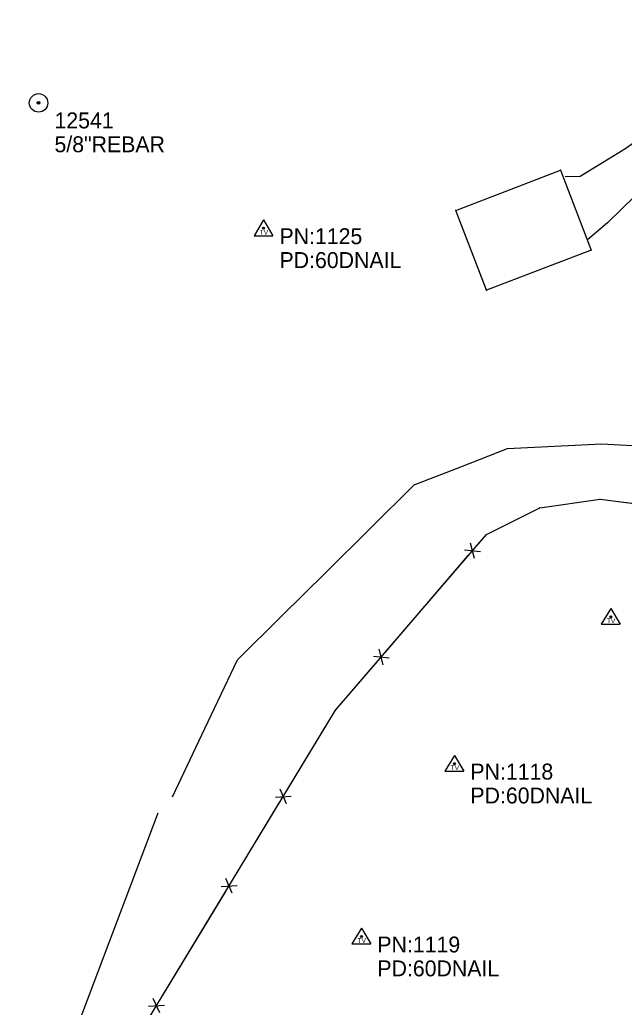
# Model space of a CAD drawing. Extents: x 1050807 to 1053552, y 395828 to 398415.
# Drawn here: x 1051876 to 1052065.9, y 397198.7 to 397508.9 of the extents above; entities that cross this region are included whole.
import ezdxf

# ---------------------------------------------------------------- set-up
doc = ezdxf.new("R2010")
doc.units = 0
for name, color, linetype in [('S_BUILDING', 7, 'Continuous'), ('S_DITCHLINE', 7, 'Continuous'), ('S_DRIVEWAY', 7, 'Continuous'), ('S_FENCE', 7, 'Continuous'), ('S_IRON_PIN', 7, 'Continuous'), ('S_IRON_PIN_ANNOT', 7, 'Continuous'), ('S_MSC_PT_SYM', 7, 'Continuous'), ('S_SECONDARY_CTL', 7, 'Continuous'), ('S_SECONDARY_CTL_ANNOT', 7, 'Continuous'), ('S_STR_PT_SYM', 7, 'Continuous')]:
    doc.layers.add(name, color=color, linetype=linetype)

msp = doc.modelspace()

# ---------------------------------------------------------------- linework, layer by layer
at = {"layer": 'S_BUILDING'}
for p, q in [((1052012.94, 397449.05), (1052045.8, 397461.69)), ((1052045.8, 397461.69), (1052055.46, 397436.58)), ((1052022.48, 397424.27), (1052012.94, 397449.05)), ((1052022.6, 397423.94), (1052012.94, 397449.05)), ((1052055.46, 397436.58), (1052022.6, 397423.94))]:
    msp.add_line(p, q, dxfattribs=at)
at = {"layer": 'S_DITCHLINE'}
for points in [[(1051923.97, 397264.82), (1051934.15, 397286.32), (1051944.33, 397307.83), (1051958.22, 397321.57), (1051972.1, 397335.31), (1051985.98, 397349.06), (1051999.87, 397362.8), (1052014.51, 397368.54), (1052029.14, 397374.28), (1052043.96, 397375.01), (1052058.77, 397375.75), (1052082, 397374.5), (1052105.23, 397373.25), (1052125.17, 397384.42), (1052145.11, 397395.59), (1052158.93, 397404.03), (1052172.75, 397412.47), (1052180.81, 397417.01)], [(1051875.96, 397128.93), (1051879.28, 397151.76), (1051885.74, 397169.79), (1051892.2, 397187.82), (1051899.01, 397205.81), (1051905.81, 397223.8), (1051912.61, 397241.79), (1051919.41, 397259.77)]]:
    msp.add_lwpolyline(points, dxfattribs=at)
at = {"layer": 'S_DRIVEWAY'}
for points in [[(1052145.24, 397508.93), (1052124, 397500.53), (1052103.96, 397490.66), (1052083.92, 397480.8), (1052066, 397468.26), (1052052.01, 397459.72), (1052047.34, 397459.64)], [(1052148.91, 397496.27), (1052135.7, 397491.43), (1052122.5, 397486.6), (1052110.72, 397480.8), (1052098.93, 397475), (1052087.27, 397468.16), (1052073.58, 397457.8), (1052060.55, 397445.18), (1052054.3, 397439.83)]]:
    msp.add_lwpolyline(points, dxfattribs=at)
at = {"layer": 'S_FENCE'}
for p, q in [((1052022.59, 397347.28), (1052039.3, 397355.63)), ((1052039.3, 397355.63), (1052058.28, 397358.31)), ((1052058.28, 397358.31), (1052107.7, 397352.14)), ((1051975.19, 397292.08), (1052022.59, 397347.28)), ((1052018.81, 397339.73), (1052017.57, 397344.57)), ((1052018.81, 397339.73), (1052017.57, 397344.57)), ((1052015.7, 397342.4), (1052020.67, 397341.91)), ((1052015.7, 397342.4), (1052020.67, 397341.91)), ((1051987.04, 397309.02), (1051992.01, 397308.52)), ((1051987.04, 397309.02), (1051992.01, 397308.52)), ((1051990.14, 397306.35), (1051988.9, 397311.19)), ((1051990.14, 397306.35), (1051988.9, 397311.19)), ((1051947.34, 397246.14), (1051975.19, 397292.08)), ((1051959.75, 397262.65), (1051957.73, 397267.23)), ((1051959.75, 397262.65), (1051957.73, 397267.23)), ((1051956.25, 397264.78), (1051961.23, 397265.1)), ((1051956.25, 397264.78), (1051961.23, 397265.1)), ((1051907.52, 397180.44), (1051947.34, 397246.14)), ((1051942.73, 397234.58), (1051940.71, 397239.15)), ((1051942.73, 397234.58), (1051940.71, 397239.15)), ((1051939.23, 397236.7), (1051944.22, 397237.03)), ((1051939.23, 397236.7), (1051944.22, 397237.03)), ((1051919.93, 397196.96), (1051917.91, 397201.54)), ((1051919.93, 397196.96), (1051917.91, 397201.54)), ((1051916.43, 397199.08), (1051921.42, 397199.41)), ((1051916.43, 397199.08), (1051921.42, 397199.41))]:
    msp.add_line(p, q, dxfattribs=at)
for points in [[(1052022.59, 397347.28), (1052039.3, 397355.63)], [(1052022.59, 397347.28), (1052039.3, 397355.63)], [(1052039.3, 397355.63), (1052058.28, 397358.31)], [(1052039.3, 397355.63), (1052058.28, 397358.31)], [(1052058.28, 397358.31), (1052078.13, 397355.83)], [(1052058.28, 397358.31), (1052078.13, 397355.83)], [(1052019.12, 397343.24), (1052022.59, 397347.28)], [(1052019.12, 397343.24), (1052022.59, 397347.28)], [(1051990.83, 397310.29), (1052016.88, 397340.64)], [(1051990.83, 397310.29), (1052016.88, 397340.64)], [(1051975.19, 397292.08), (1051988.22, 397307.25)], [(1051975.19, 397292.08), (1051988.22, 397307.25)], [(1051959.78, 397266.65), (1051975.19, 397292.08)], [(1051959.78, 397266.65), (1051975.19, 397292.08)], [(1051947.34, 397246.14), (1051957.7, 397263.23)], [(1051947.34, 397246.14), (1051957.7, 397263.23)], [(1051942.46, 397238.09), (1051947.34, 397246.14)], [(1051942.46, 397238.09), (1051947.34, 397246.14)], [(1051919.96, 397200.96), (1051940.68, 397235.15)], [(1051919.96, 397200.96), (1051940.68, 397235.15)]]:
    msp.add_lwpolyline(points, dxfattribs=at)
at = {"layer": 'S_IRON_PIN'}
for radius in [2.91, 0.411, 0.262, 0.212, 0.145, 0.0822, 0.0581]:
    msp.add_circle((1051881.87, 397482.81), radius, dxfattribs=at)
at = {"layer": 'S_MSC_PT_SYM'}
for points in [[(1052039.3, 397355.63), (1052039.3, 397355.68), (1052039.3, 397355.63), (1052039.25, 397355.63), (1052039.3, 397355.63), (1052039.3, 397355.58), (1052039.3, 397355.63), (1052039.35, 397355.63)], [(1052058.28, 397358.31), (1052058.28, 397358.36), (1052058.28, 397358.31), (1052058.23, 397358.31), (1052058.28, 397358.31), (1052058.28, 397358.26), (1052058.28, 397358.31), (1052058.33, 397358.31)], [(1052022.59, 397347.28), (1052022.59, 397347.33), (1052022.59, 397347.28), (1052022.54, 397347.28), (1052022.59, 397347.28), (1052022.59, 397347.23), (1052022.59, 397347.28), (1052022.64, 397347.28)], [(1051975.19, 397292.08), (1051975.19, 397292.13), (1051975.19, 397292.08), (1051975.14, 397292.08), (1051975.19, 397292.08), (1051975.19, 397292.03), (1051975.19, 397292.08), (1051975.24, 397292.08)], [(1051947.34, 397246.14), (1051947.34, 397246.19), (1051947.34, 397246.14), (1051947.29, 397246.14), (1051947.34, 397246.14), (1051947.34, 397246.09), (1051947.34, 397246.14), (1051947.39, 397246.14)]]:
    msp.add_lwpolyline(points, dxfattribs=at)
at = {"layer": 'S_SECONDARY_CTL'}
for p, q in [((1051952.56, 397446.05), (1051949.55, 397441.1)), ((1051952.56, 397446.05), (1051955.51, 397441.1)), ((1051949.55, 397441.1), (1051955.51, 397441.1)), ((1052061.61, 397324.02), (1052058.6, 397319.07)), ((1052061.61, 397324.02), (1052064.56, 397319.07)), ((1052058.6, 397319.07), (1052064.56, 397319.07)), ((1052012.53, 397277.87), (1052009.52, 397272.91)), ((1052012.53, 397277.87), (1052015.48, 397272.91)), ((1052009.52, 397272.91), (1052015.48, 397272.91)), ((1051983.31, 397223.57), (1051980.3, 397218.62)), ((1051983.31, 397223.57), (1051986.26, 397218.62)), ((1051980.3, 397218.62), (1051986.26, 397218.62))]:
    msp.add_line(p, q, dxfattribs=at)
for centre, radius in [((1051952.56, 397443.44), 0.311), ((1051952.56, 397443.44), 0.183), ((1051952.56, 397443.44), 0.103), ((1052061.61, 397321.41), 0.311), ((1052061.61, 397321.41), 0.183), ((1052061.61, 397321.41), 0.103), ((1052012.53, 397275.26), 0.311), ((1052012.53, 397275.26), 0.183), ((1052012.53, 397275.26), 0.103), ((1051983.31, 397220.96), 0.311), ((1051983.31, 397220.96), 0.183), ((1051983.31, 397220.96), 0.103)]:
    msp.add_circle(centre, radius, dxfattribs=at)
at = {"layer": 'S_STR_PT_SYM'}
for points in [[(1052045.8, 397461.69), (1052045.8, 397461.74), (1052045.8, 397461.69), (1052045.75, 397461.69), (1052045.8, 397461.69), (1052045.8, 397461.64), (1052045.8, 397461.69), (1052045.85, 397461.69)], [(1052012.94, 397449.05), (1052012.94, 397449.1), (1052012.94, 397449.05), (1052012.89, 397449.05), (1052012.94, 397449.05), (1052012.94, 397449), (1052012.94, 397449.05), (1052012.99, 397449.05)], [(1052012.94, 397449.05), (1052012.94, 397449.1), (1052012.94, 397449.05), (1052012.89, 397449.05), (1052012.94, 397449.05), (1052012.94, 397449), (1052012.94, 397449.05), (1052012.99, 397449.05)], [(1052055.46, 397436.58), (1052055.46, 397436.63), (1052055.46, 397436.58), (1052055.41, 397436.58), (1052055.46, 397436.58), (1052055.46, 397436.53), (1052055.46, 397436.58), (1052055.51, 397436.58)], [(1052022.48, 397424.27), (1052022.48, 397424.32), (1052022.48, 397424.27), (1052022.43, 397424.27), (1052022.48, 397424.27), (1052022.48, 397424.22), (1052022.48, 397424.27), (1052022.53, 397424.27)], [(1052022.6, 397423.94), (1052022.6, 397423.99), (1052022.6, 397423.94), (1052022.55, 397423.94), (1052022.6, 397423.94), (1052022.6, 397423.89), (1052022.6, 397423.94), (1052022.65, 397423.94)]]:
    msp.add_lwpolyline(points, dxfattribs=at)

# ---------------------------------------------------------------- texts
at = {"layer": 'S_IRON_PIN_ANNOT'}
for s, p in [('12541', (1051886.87, 397474.81)), ('5/8"REBAR', (1051886.87, 397467.31))]:
    msp.add_text(s, height=5, dxfattribs=at).set_placement(p)
at = {"layer": 'S_SECONDARY_CTL'}
for p in [(1051951.36, 397441.43), (1052060.41, 397319.4), (1052011.33, 397273.24), (1051982.1, 397218.95)]:
    msp.add_text('TV', height=1.5, dxfattribs=at).set_placement(p)
at = {"layer": 'S_SECONDARY_CTL_ANNOT'}
for s, p in [('PN:1125', (1051957.56, 397438.44)), ('PD:60DNAIL', (1051957.56, 397430.94)), ('PN:1118', (1052017.53, 397270.26)), ('PD:60DNAIL', (1052017.53, 397262.76)), ('PN:1119', (1051988.31, 397215.96)), ('PD:60DNAIL', (1051988.31, 397208.46))]:
    msp.add_text(s, height=5, dxfattribs=at).set_placement(p)

doc.saveas('drawing.dxf')
